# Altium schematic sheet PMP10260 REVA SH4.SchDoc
size 431 x 279 mm; Date: Not shown in title block; ApprovedBy: Not shown in title block; CheckedBy: Not shown in title block; Author: Not shown in title block; CompanyName: Not shown in title block; Engineer: Not shown in title block; Organization: Not shown in title block; Address1: Not shown in title block; Address2: Not shown in title block; Address3: Not shown in title block; Address4: Not shown in title block; DocumentNumber: 4; Revision: Use project parameter SCH_Rev; SheetNumber: 4; SheetTotal: 4; PageSetup: Record=PageOptions|CenterHorizontal=True|CenterVertical=True|PrintScale=1.00|XCorrection=1.00|YCorrection=1.00|PrintKind=0|BorderSize=5000000|LeftOffset=0|BottomOffset=0|Orientation=2|PaperLength=1000|PaperWidth=1000|Scale=100|PaperSource=15|PrintQuality=600|MediaType=1|DitherType=10|PaperKind=Letter|PrintScaleMode=1
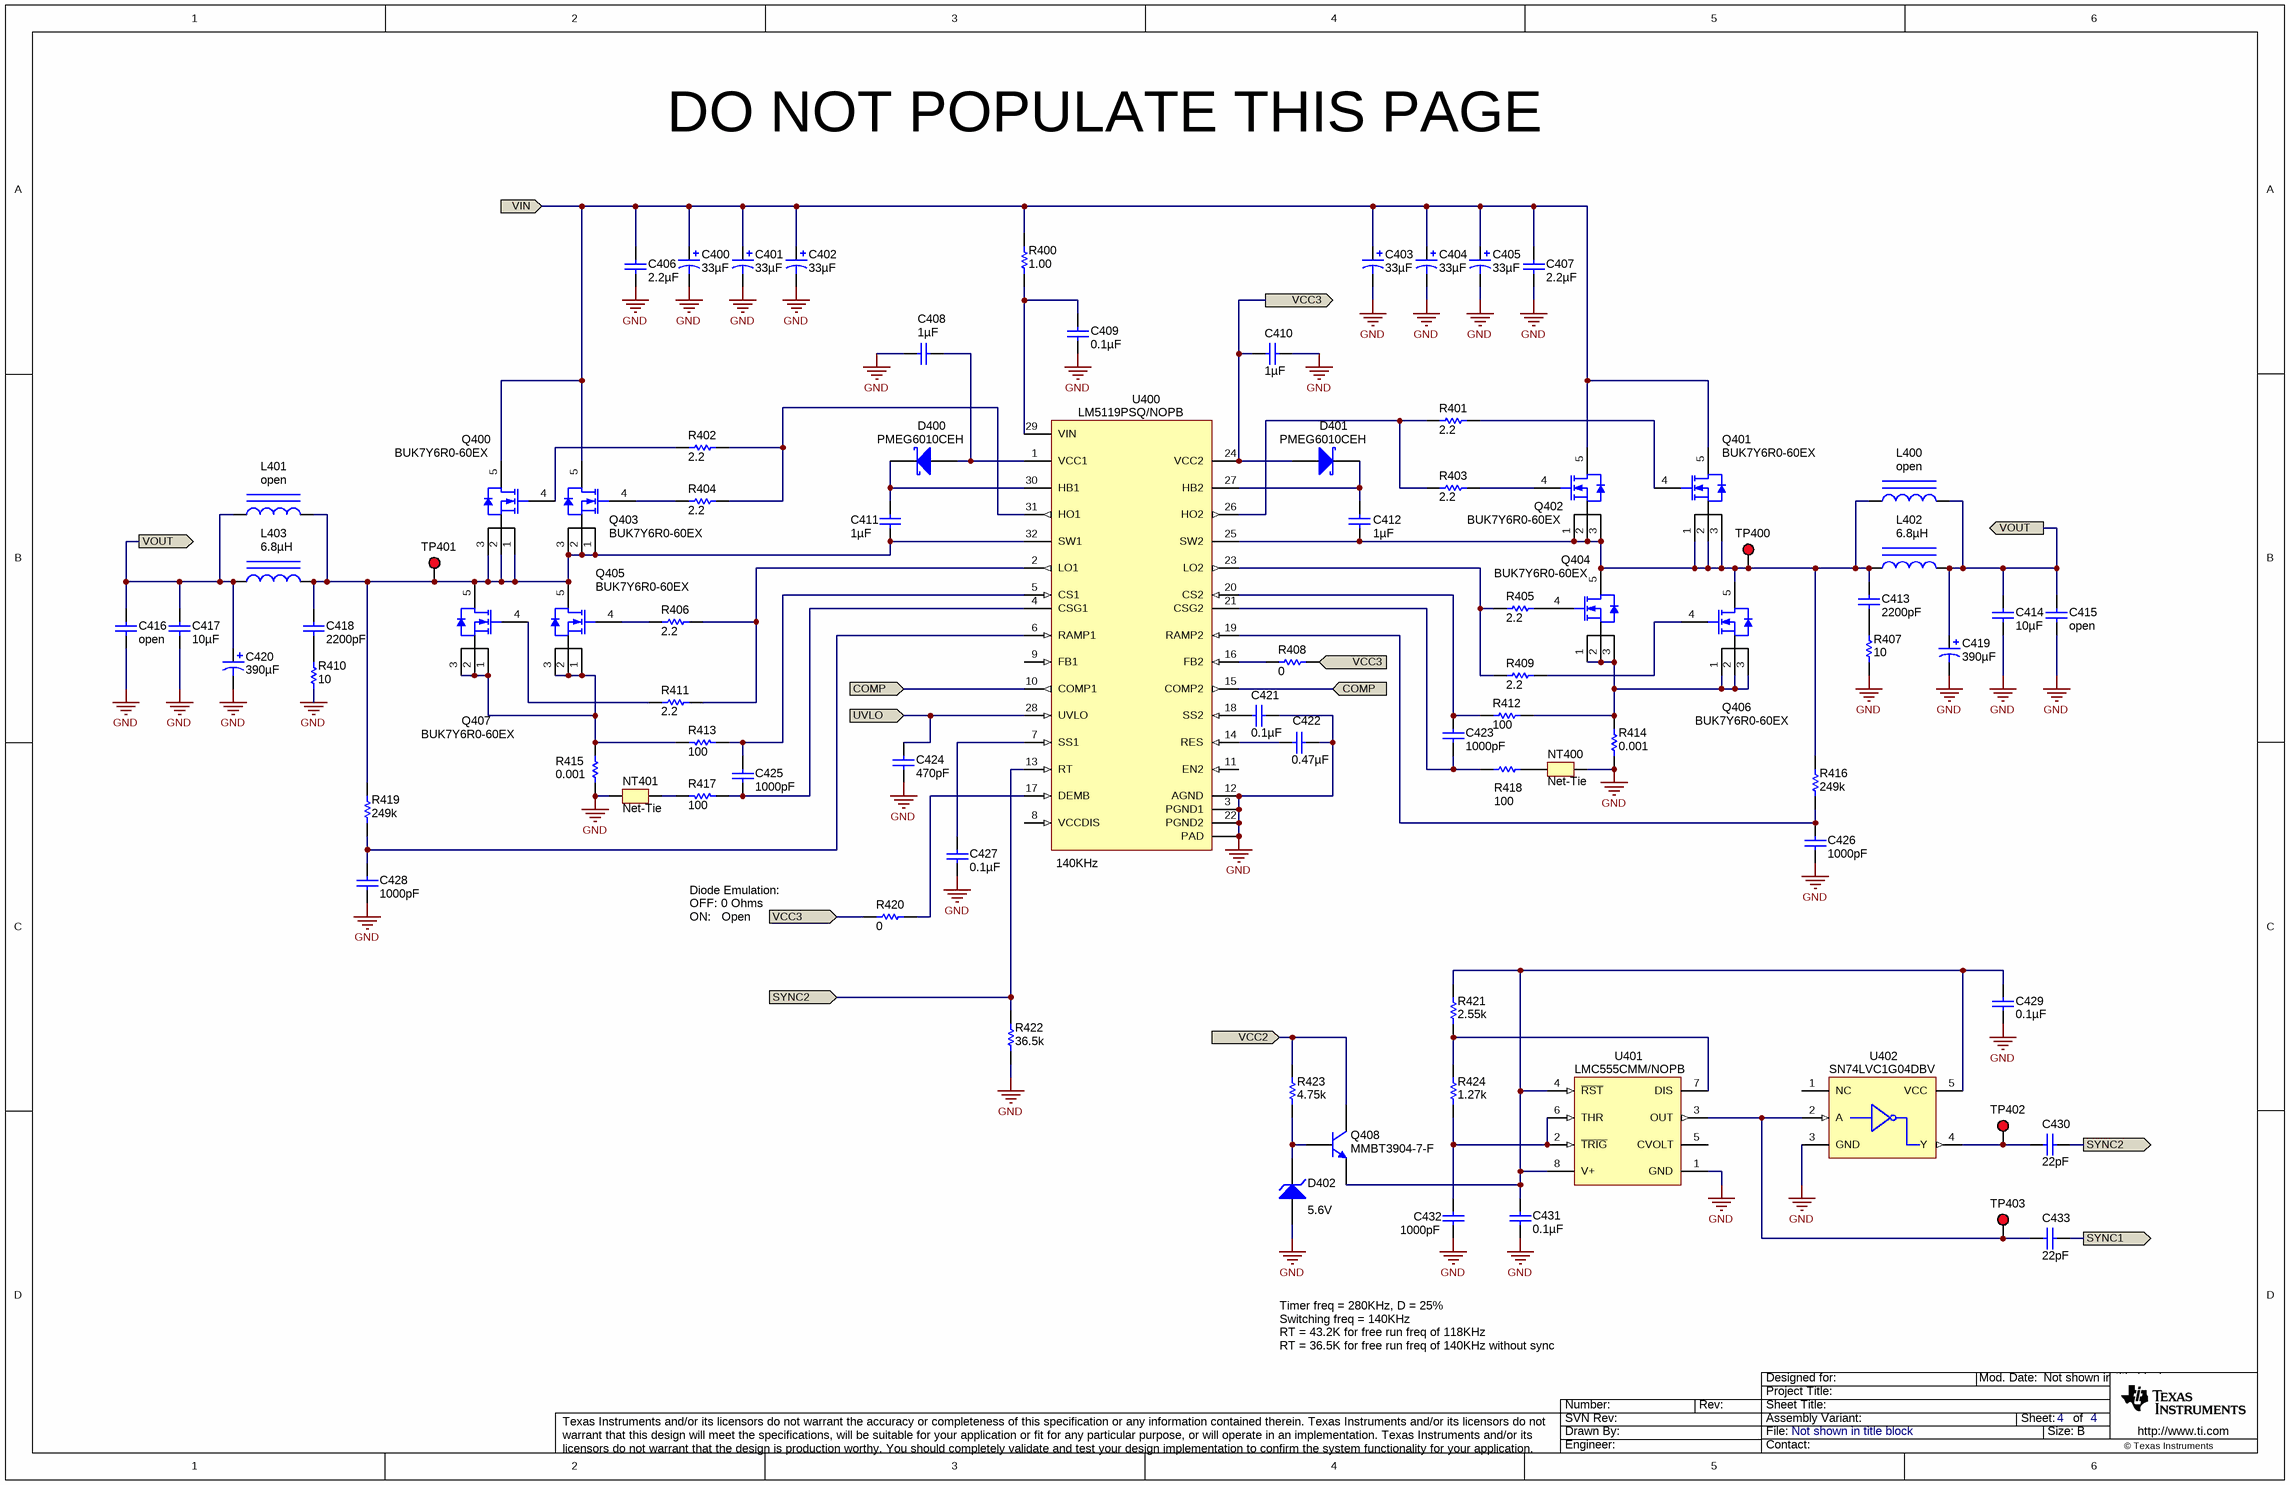
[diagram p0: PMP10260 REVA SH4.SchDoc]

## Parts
C400  ValueDisplayed: 33µF  [SXV_E12]  (hidden comment: 63SXV33M)
C401  ValueDisplayed: 33µF  [SXV_E12]  (hidden comment: 63SXV33M)
C402  ValueDisplayed: 33µF  [SXV_E12]  (hidden comment: 63SXV33M)
C403  ValueDisplayed: 33µF  [SXV_E12]  (hidden comment: 63SXV33M)
C404  ValueDisplayed: 33µF  [SXV_E12]  (hidden comment: 63SXV33M)
C405  ValueDisplayed: 33µF  [SXV_E12]  (hidden comment: 63SXV33M)
C406  ValueDisplayed: 2.2µF  [1210]  (hidden comment: GRM32ER72A225KA35L)
C407  ValueDisplayed: 2.2µF  [1210]  (hidden comment: GRM32ER72A225KA35L)
C408  ValueDisplayed: 1µF  [0603L]  (hidden comment: C1608X7R1E105K080AB)
C409  ValueDisplayed: 0.1µF  [0805_HV]  (hidden comment: C2012X7R2A104K)
C410  ValueDisplayed: 1µF  [0603L]  (hidden comment: C1608X7R1E105K080AB)
C411  ValueDisplayed: 1µF  [0603L]  (hidden comment: C1608X7R1E105K080AB)
C412  ValueDisplayed: 1µF  [0603L]  (hidden comment: C1608X7R1E105K080AB)
C413  ValueDisplayed: 2200pF  [0603L]  (hidden comment: C0603C222K5RAC)
C414  ValueDisplayed: 10µF  [1210L]  (hidden comment: GMK325AB7106MM-T)
C415  ValueDisplayed: open  [1210]
C416  ValueDisplayed: open  [1210]
C417  ValueDisplayed: 10µF  [1210L]  (hidden comment: GMK325AB7106MM-T)
C418  ValueDisplayed: 2200pF  [0603L]  (hidden comment: C0603C222K5RAC)
C419  ValueDisplayed: 390µF  [SM_RADIAL_8MM]  (hidden comment: 20SVPF390M)
C420  ValueDisplayed: 390µF  [SM_RADIAL_8MM]  (hidden comment: 20SVPF390M)
C421  ValueDisplayed: 0.1µF  [0603L]  (hidden comment: C1608X7R1H104K)
C422  ValueDisplayed: 0.47µF  [0603L]  (hidden comment: C0603C474K4RACTU)
C423  ValueDisplayed: 1000pF  [0603]  (hidden comment: C1608C0G1H102J)
C424  ValueDisplayed: 470pF  [0603]  (hidden comment: C1608C0G1H471J)
C425  ValueDisplayed: 1000pF  [0603]  (hidden comment: C1608C0G1H102J)
C426  ValueDisplayed: 1000pF  [0603]  (hidden comment: C1608C0G1H102J)
C427  ValueDisplayed: 0.1µF  [0603L]  (hidden comment: C1608X7R1H104K)
C428  ValueDisplayed: 1000pF  [0603]  (hidden comment: C1608C0G1H102J)
C429  ValueDisplayed: 0.1µF  [0805_HV]  (hidden comment: C2012X7R2A104K)
C430  ValueDisplayed: 22pF  [0603]  (hidden comment: C1608C0G1H220J)
C431  ValueDisplayed: 0.1µF  [0805_HV]  (hidden comment: C2012X7R2A104K)
C432  ValueDisplayed: 1000pF  [0603]  (hidden comment: C1608C0G1H102J)
C433  ValueDisplayed: 22pF  [0603]  (hidden comment: C1608C0G1H220J)
D400  PMEG6010CEH  [SOD-123F]
D401  PMEG6010CEH  [SOD-123F]
D402  value 5.6V  [SOD-123]  (hidden comment: MMSZ5232B-7-F)
L400  ValueDisplayed: open  [XAL1510]
L401  ValueDisplayed: open  [XAL1510]
L402  ValueDisplayed: 6.8µH  [SER2915]  (hidden comment: SER2915H-682KL)
L403  ValueDisplayed: 6.8µH  [SER2915]  (hidden comment: SER2915H-682KL)
NT400  Net-Tie  [Net-Tie_10mil]  (net tie, no BOM)
NT401  Net-Tie  [Net-Tie_10mil]  (net tie, no BOM)
Q400  BUK7Y6R0-60EX  [LFPAK56]
Q401  BUK7Y6R0-60EX  [LFPAK56]
Q402  BUK7Y6R0-60EX  [LFPAK56]
Q403  BUK7Y6R0-60EX  [LFPAK56]
Q404  BUK7Y6R0-60EX  [LFPAK56]
Q405  BUK7Y6R0-60EX  [LFPAK56]
Q406  BUK7Y6R0-60EX  [LFPAK56]
Q407  BUK7Y6R0-60EX  [LFPAK56]
Q408  MMBT3904-7-F  [SOT-23]
R400  value 1.00  [0805_HV]  (hidden comment: CRCW08051R00FKEA)
R401  value 2.2  [0603L]  (hidden comment: CRCW06032R20JNEA)
R402  value 2.2  [0603L]  (hidden comment: CRCW06032R20JNEA)
R403  value 2.2  [0603L]  (hidden comment: CRCW06032R20JNEA)
R404  value 2.2  [0603L]  (hidden comment: CRCW06032R20JNEA)
R405  value 2.2  [0603L]  (hidden comment: CRCW06032R20JNEA)
R406  value 2.2  [0603L]  (hidden comment: CRCW06032R20JNEA)
R407  value 10  [2010M]  (hidden comment: CRCW201010R0JNEFHP)
R408  value 0  [0603L]  (hidden comment: CRCW06030000Z0EA)
R409  value 2.2  [0603L]  (hidden comment: CRCW06032R20JNEA)
R410  value 10  [2010M]  (hidden comment: CRCW201010R0JNEFHP)
R411  value 2.2  [0603L]  (hidden comment: CRCW06032R20JNEA)
R412  value 100  [0603L]  (hidden comment: RC0603FR-07100RL)
R413  value 100  [0603L]  (hidden comment: RC0603FR-07100RL)
R414  value 0.001  [2512M]  (hidden comment: ERJ-M1WTF1M0U)
R415  value 0.001  [2512M]  (hidden comment: ERJ-M1WTF1M0U)
R416  value 249k  [0603]  (hidden comment: CRCW0603249KFKEA)
R417  value 100  [0603L]  (hidden comment: RC0603FR-07100RL)
R418  value 100  [0603L]  (hidden comment: RC0603FR-07100RL)
R419  value 249k  [0603]  (hidden comment: CRCW0603249KFKEA)
R420  value 0  [0603L]  (hidden comment: CRCW06030000Z0EA)
R421  value 2.55k  [0603]  (hidden comment: CRCW06032K55FKEA)
R422  value 36.5k  [0603]  (hidden comment: CRCW060336K5FKEA)
R423  value 4.75k  [0603]  (hidden comment: CRCW06034K75FKEA)
R424  value 1.27k  [0603]  (hidden comment: CRCW06031K27FKEA)
TP400  5010  [Keystone5010]  (value not drawn)
TP401  5010  [Keystone5010]  (value not drawn)
TP402  5010  [Keystone5010]  (value not drawn)
TP403  5010  [Keystone5010]  (value not drawn)
U400  LM5119PSQ/NOPB  [RTV0032A]
U401  LMC555CMM/NOPB  [MUA08A_N]
U402  SN74LVC1G04DBV  [DBV0005A_N]

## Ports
COMP, SYNC1, SYNC2, UVLO, VCC2, VCC3, VIN, VOUT

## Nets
GND: C400.2(-) C401.2(-) C402.2(-) C403.2(-) C404.2(-) C405.2(-) C406.2 C407.2 C408.2 C409.2 C410.2 C414.2 C415.2 C416.2 C417.2 C419.2(-) C420.2(-) C421.1 C422.1 C424.2 C426.2 C427.2 C428.2 C429.2 C431.2 C432.2 D402.2(A) NT400.2 NT401.1 R407.1 R410.1 R414.1 R415.1 R422.1 U400.3(PGND1) U400.12(AGND) U400.22(PGND2) U400.33(PAD) U401.1(GND) U402.3(GND)
COMP: U400.10(COMP1) U400.15(COMP2) ; port COMP
SYNC1: C433.1 ; port SYNC1
SYNC2: C430.1 R422.2 U400.13(RT) ; port SYNC2
UVLO: C424.1 U400.28(UVLO) ; port UVLO
VCC2: Q408.3(C) R423.2 ; port VCC2
VCC3: C410.1 D401.2(A) R408.2 R420.1 U400.24(VCC2) ; port VCC3
VIN: C400.1(+) C401.1(+) C402.1(+) C403.1(+) C404.1(+) C405.1(+) C406.1 C407.1 Q400.5(D) Q401.5(D) Q402.5(D) Q403.5(D) R400.1 ; port VIN
VOUT: C414.1 C415.1 C416.1 C417.1 C419.1(+) C420.1(+) L400.2 L401.1 L402.2 L403.1 ; port VOUT
NetC408_1: C408.1 D400.2(A) U400.1(VCC1)
NetC409_1: C409.1 R400.2 U400.29(VIN)
NetC411_1: C411.1 D400.1(K) U400.30(HB1)
NetC411_2: C411.2 C418.1 L401.2 L403.2 Q400.1(S) Q400.2(S) Q400.3(S) Q403.1(S) Q403.2(S) Q403.3(S) Q405.5(D) Q407.5(D) R419.2 TP401.1 U400.32(SW1)
NetC412_1: C412.1 D401.1(K) U400.27(HB2)
NetC412_2: C412.2 C413.1 L400.1 L402.1 Q401.1(S) Q401.2(S) Q401.3(S) Q402.1(S) Q402.2(S) Q402.3(S) Q404.5(D) Q406.5(D) R416.2 TP400.1 U400.25(SW2)
NetC413_2: C413.2 R407.2
NetC418_2: C418.2 R410.2
NetC421_2: C421.2 U400.18(SS2)
NetC422_2: C422.2 U400.14(RES)
NetC423_1: C423.1 R412.1 U400.20(CS2)
NetC423_2: C423.2 R418.1 U400.21(CSG2)
NetC425_1: C425.1 R413.1 U400.5(CS1)
NetC425_2: C425.2 R417.1 U400.4(CSG1)
NetC426_1: C426.1 R416.1 U400.19(RAMP2)
NetC427_1: C427.1 U400.7(SS1)
NetC428_1: C428.1 R419.1 U400.6(RAMP1)
NetC429_1: C429.1 C431.1 Q408.2(E) R421.2 U401.4(~{RST}) U401.8(V+) U402.5(VCC)
NetC430_2: C430.2 TP402.1 U402.4(Y)
NetC432_1: C432.1 R424.1 U401.2(~{TRIG}) U401.6(THR)
NetC433_2: C433.2 TP403.1 U401.3(OUT) U402.2(A)
NetD402_1: D402.1(K) Q408.1(B) R423.1
NetNT400_1: NT400.1 R418.2
NetNT401_2: NT401.2 R417.2
NetQ400_4: Q400.4(G) R402.1
NetQ401_4: Q401.4(G) R401.2
NetQ402_4: Q402.4(G) R403.2
NetQ403_4: Q403.4(G) R404.1
NetQ404_1: Q404.1(S) Q404.2(S) Q404.3(S) Q406.1(S) Q406.2(S) Q406.3(S) R412.2 R414.2
NetQ404_4: Q404.4(G) R405.2
NetQ405_1: Q405.1(S) Q405.2(S) Q405.3(S) Q407.1(S) Q407.2(S) Q407.3(S) R413.2 R415.2
NetQ405_4: Q405.4(G) R406.1
NetQ406_4: Q406.4(G) R409.2
NetQ407_4: Q407.4(G) R411.1
NetR401_1: R401.1 R403.1 U400.26(HO2)
NetR402_2: R402.2 R404.2 U400.31(HO1)
NetR405_1: R405.1 R409.1 U400.23(LO2)
NetR406_2: R406.2 R411.2 U400.2(LO1)
NetR408_1: R408.1 U400.16(FB2)
NetR420_2: R420.2 U400.17(DEMB)
NetR421_1: R421.1 R424.2 U401.7(DIS)

Not connected (* = marked no-connect by the designer): U400 8(VCCDIS) 9(FB1) 11(EN2); U401 5(CVOLT); U402 1(NC)

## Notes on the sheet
- DO NOT POPULATE THIS PAGE
- Diode Emulation:
- OFF: 0 Ohms
- (near U400) 140KHz
- ON:   Open
- Timer freq = 280KHz, D = 25%
- Switching freq = 140KHz
- RT = 43.2K for free run freq of 118KHz
- RT = 36.5K for free run freq of 140KHz without sync

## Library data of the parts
C400-C405 = 63SXV33M: CAP, OS-CON, 33uF, 63V, +/-20%, 0.025 ohm, 8.0x11.9mm SMD; Manufacturer: Panasonic; Polarized: Y; CompType: Capacitor; U/M: EA; Cap_F: 0.000033; Tolerance_%: 20; VDC_V: 63; ESR_Ohm: 0.025; IRMS_A: 2.95; TaMin_C: -55; TaMax_C: 105
C406 C407 = GRM32ER72A225KA35L: CAP, CERM, 2.2uF, 100V, +/-10%, X7R, 1210; Manufacturer: MuRata; Polarized: N; CompType: Capacitor; U/M: EA; Cap_F: 0.0000022; Tolerance_%: 10; ESR_Ohm: 0.007; Value1: 0.007 ohm; VDC_V: 100; IRMS_A: 4.4; TaMin_C: -55; TaMax_C: 125
C408 C410-C412 = C1608X7R1E105K080AB: CAP, CERM, 1uF, 25V, +/-10%, X7R, 0603; Manufacturer: TDK; Polarized: N; CompType: Capacitor; U/M: EA; Cap_F: 0.000001; Tolerance_%: 10; Value1: Unknown; VDC_V: 25; TaMin_C: -55; TaMax_C: 125; Cap_Case: 0603
C409 C429 C431 = C2012X7R2A104K: CAP, CERM, 0.1uF, 100V, +/-10%, X7R, 0805; Manufacturer: TDK; Polarized: N; CompType: Capacitor; U/M: EA; Cap_F: 0.0000001; Tolerance_%: 10; ESR_Ohm: 0.0158; Value1: 0.0158 ohm; VDC_V: 100; TaMin_C: -55; TaMax_C: 125; Cap_Case: 0805
C413 C418 = C0603C222K5RAC: CAP, CERM, 2200pF, 50V, +/-10%, X7R, 0603; Manufacturer: Kemet; Polarized: N; CompType: Capacitor; U/M: EA; Cap_F: 0.0000000022; Tolerance_%: 10; Value1: Unknown; VDC_V: 50; TaMin_C: -55; TaMax_C: 125; Cap_Case: 0603
C414 C417 = GMK325AB7106MM-T: CAP, CERM, 10uF, 35V, +/-20%, X7R, 1206; Manufacturer: Taiyo Yuden; Polarized: N; CompType: Capacitor; U/M: EA; Cap_F: 0.00001; Tolerance_%: 20; Value1: Unknown; VDC_V: 35; TaMin_C: -55; TaMax_C: 125; Cap_Case: 1210
C415 C416 = C3225X7R1H335M: CAP, CERM, open, 1210; Manufacturer: TDK; Polarized: N; CompType: Capacitor; Value: 10uF; U/M: EA; Cap_F: 0.0000033; Tolerance_%: 20; Value1: Unknown; VDC_V: 50; Value2: 50V; TempCo: X5R; TaMin_C: -55; TaMax_C: 125
C419 C420 = 20SVP100M: CAP, OS-CON, 390uF, 20V, +/-20%, 0.014 ohm, 8x10 SMD; Manufacturer: Sanyo; Polarized: Y; CompType: Capacitor; U/M: EA; Cap_F: 0.0001; Tolerance_%: 20; ESR_Ohm: 0.024; IRMS_A: 3.32; TaMin_C: -55; TaMax_C: 105; Cap_Case: 8.3x8.3x11.9
C421 C427 = C1608X7R1H104K: CAP, CERM, 0.1uF, 50V, +/-10%, X7R, 0603; Manufacturer: TDK; Polarized: N; CompType: Capacitor; U/M: EA; Cap_F: 0.0000001; Tolerance_%: 10; ESR_Ohm: 0.017; Value1: 0.017 ohm; VDC_V: 50; TaMin_C: -55; TaMax_C: 125; Cap_Case: 0603
C422 = C0603C474K4RACTU: CAP, CERM, 0.47uF, 16V, +/-10%, X7R, 0603; Manufacturer: Kemet; Polarized: N; CompType: Capacitor; U/M: EA; Cap_F: 0.00000047; Tolerance_%: 10; Value1: Unknown; VDC_V: 16; TaMin_C: -55; TaMax_C: 125; Cap_Case: 0603
C423 C425 C426 C428 C432 = C1608C0G1H102J: CAP, CERM, 1000pF, 50V, +/-5%, C0G/NP0, 0603; Manufacturer: TDK; Polarized: N; CompType: Capacitor; U/M: EA; Cap_F: 0.000000001; Tolerance_%: 5; ESR_Ohm: 0.0563; Value1: 0.0563 ohm; VDC_V: 50; TaMin_C: -55; TaMax_C: 125
C424 = C1608C0G1H471J: CAP, CERM, 470pF, 50V, +/-5%, C0G/NP0, 0603; Manufacturer: TDK; Polarized: N; CompType: Capacitor; U/M: EA; Cap_F: 0.00000000047; Tolerance_%: 5; ESR_Ohm: 0.0922; Value1: 0.0922 ohm; VDC_V: 50; TaMin_C: -55; TaMax_C: 125
C430 C433 = C1608C0G1H220J: CAP, CERM, 22pF, 50V, +/-5%, C0G/NP0, 0603; Manufacturer: TDK; Polarized: N; CompType: Capacitor; U/M: EA; Cap_F: 0.000000000022; Tolerance_%: 5; ESR_Ohm: 0.3882; Value1: 0.3882 ohm; VDC_V: 50; TaMin_C: -55; TaMax_C: 125
D400 D401 = PMEG6010CEH,115: Diode, Schottky, 60V, 1A, SOD-123F; Manufacturer: NXP Semiconductor; U/M: EA; Vf_V: 0.57; Value2: 0.57V; Io_A: 1; Vr_V: 60; TJmax_C: 150
D402 = MMSZ5232B-7-F: Diode, Zener, 5.6V, 500mW, SOD-123; Manufacturer: Diodes Inc.; SymbolCreator: a0412235; U/M: EA; Power_W: 0.5; Vz_V: 5.6; Value1: 0.5W; RJA_CperW: 350
L400 L401 = XAL1510-682MEB: Inductor, Shielded, Composite, 6.8uH, 26A, 0.00417 ohm, SMD; Ind_H: 6.8E-6; Imax_A: 26; Irms: 26A @ 40C rise; Isat: 36A @ 30% inductance drop; U/M: EA
L402 L403 = SER2915H-682KL: Inductor, Shielded E Core, Ferrite, 6.8uH, 30A, 0.00186 ohm, SMD; Manufacturer: Coilcraft; Ind_H: 6.8E-6; Imax_A: 30; Irms: 30A @ 40C rise; Isat: 36.2A @ 30% inductance drop; U/M: EA
NT400 NT401 = Net-Tie: Single point connection between nets.; SymbolCreator: codlsc
Q400-Q407 = BUK7Y6R0-60EX: MOSFET, N-CH, 60V, 100A, SOT669; Manufacturer: NXP Semiconductor; Alternate Manufacturer: None; SymbolCreator: a0412235; U/M: EA; ChType: N; VdsMax_V: 60; Value1: ? ohm; Value2: 45.4 nC; QgTyp_nC: 45.4; Vgs_V: 20; IdsMax_A: 100
Q408 = MMBT3904-7-F, Diodes Inc.: Transistor, NPN, 40V, 0.2A, SOT-23; CompType: BJT; PNP: 0; NPN: 1; Vceo_V: 40; Vcesat1_V: 0.2; Value: 0.2V; HfeMax: 400; TaMin_C: -55; TaMax_C: 150; U/M: EA
R400 = CRCW08051R00FKEA: RES, 1.00 ohm, 1%, 0.125W, 0805; Manufacturer: Vishay-Dale; CompType: Resistor; Res_ohm: 1; Value_Code: 1R00; Power_W: 0.125; VDC_V: 150; TempCo: 100 ppm/C; EIA_Code: E96; U/M: EA
R401-R406 R409 R411 = CRCW06032R20JNEA: RES, 2.2 ohm, 5%, 0.1W, 0603; Manufacturer: Vishay-Dale; CompType: Resistor; Value_Code: 2R20; Tolerance_%: 5; Power_W: 0.1; VDC_V: 75; TempCo: 200 ppm/C; EIA_Code: E24; U/M: EA
R407 R410 = CRCW20101R00JNEFHP: RES, 10 ohm, 5%, 1W, 2010; Manufacturer: Vishay-Dale; CompType: Resistor; Res_ohm: 1; Value_Code: 1R00; Tolerance_%: 5; VDC_V: 400; TempCo: 200 ppm/C; EIA_Code: E24; U/M: EA
R408 R420 = CRCW06030000Z0EA: RES, 0 ohm, 5%, 0.1W, 0603; Manufacturer: Vishay-Dale; CompType: Resistor; Value_Code: 0000; Tolerance_%: 5; Power_W: 0.1; VDC_V: 75; TempCo: 200 ppm/C; EIA_Code: E24; U/M: EA
R412 R413 R417 R418 = RC0603FR-07100RL: RES, 100 ohm, 1%, 0.1W, 0603; Manufacturer: Yageo America; CompType: Resistor; Value_Code: 100R; Tolerance_%: 1; Power_W: 0.1; VDC_V: 150; TempCo: 200 ppm/C; EIA_Code: E96; U/M: EA
R414 R415 = ERJ-M1WTF1M0U: RES, 0.001 ohm, 1%, 1W, 2512; Manufacturer: Panasonic; CompType: Resistor; Value_Code: R001; Tolerance_%: 1; TempCo: ppm/C; EIA_Code: E96; U/M: EA
R416 R419 = CRCW0603249KFKEA: RES, 249k ohm, 1%, 0.1W, 0603; Manufacturer: Vishay-Dale; CompType: Resistor; Res_ohm: 249000; Tolerance_%: 1; Power_W: 0.1; VDC_V: 75; TempCo: 100 ppm/C; EIA_Code: E96; U/M: EA
R421 = CRCW06032K55FKEA: RES, 2.55k ohm, 1%, 0.1W, 0603; Manufacturer: Vishay-Dale; CompType: Resistor; Res_ohm: 2550; Value_Code: 2k55; Tolerance_%: 1; Power_W: 0.1; VDC_V: 75; TempCo: 100 ppm/C; EIA_Code: E96; U/M: EA
R422 = CRCW060336K5FKEA: RES, 36.5k ohm, 1%, 0.1W, 0603; Manufacturer: Vishay-Dale; CompType: Resistor; Res_ohm: 36500; Value_Code: 36k5; Tolerance_%: 1; Power_W: 0.1; VDC_V: 75; TempCo: 100 ppm/C; EIA_Code: E96; U/M: EA
R423 = CRCW06034K75FKEA: RES, 4.75k ohm, 1%, 0.1W, 0603; Manufacturer: Vishay-Dale; CompType: Resistor; Res_ohm: 4750; Value_Code: 4k75; Tolerance_%: 1; Power_W: 0.1; VDC_V: 75; TempCo: 100 ppm/C; EIA_Code: E96; U/M: EA
R424 = CRCW06031K27FKEA: RES, 1.27k ohm, 1%, 0.1W, 0603; Manufacturer: Vishay-Dale; CompType: Resistor; Res_ohm: 1270; Value_Code: 1k27; Tolerance_%: 1; Power_W: 0.1; VDC_V: 75; TempCo: 100 ppm/C; EIA_Code: E96; U/M: EA
TP400-TP403 = 5010: Test Point, Multipurpose, Red, TH; Manufacturer: Keystone; CompType: Test Point Loop; U/M: EA
U400 = LM5119PSQ/NOPB: LM5119/LM5119Q Wide Input Range Dual Synchronous Buck Controller, RTV0032A; Alternate Manufacturer: None; Manufacturer: Texas Instruments; SymbolCreator: a0411947; CompType: IC; U/M: EA
U401 = LMC555CMM/NOPB: CMOS Timer, 8-pin Mini SOIC, Pb-Free; Manufacturer: National Semiconductor; PackageTopMarking: ZXTT*ZC5; PowerWise: N; CompType: Analog IC
U402 = SN74LVC1G04DBV: Single Inverter Gate, DBV0005A; Alternate Manufacturer: None; Manufacturer: Texas Instruments; SymbolCreator: a0411947; CompType: IC; U/M: EA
